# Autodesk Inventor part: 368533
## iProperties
Created: 2006-08
Part Number: 368533
Material: St
Description: Paßscheibe
Vendor: Autodesk Inc.
Document SubType Name: Modeling
Standard: DIN 988
Designer: I.Baliuc
Standards Organization: DIN
Language: de-DE
Size Designation: 25 x 35 x 0.5
Categories: <MemberInstance Version="R10.0.0"><Categories><Category DisplayName="Wellenteile" InternalName="7f7aeb1f-a693-4053-b835-cee3144e0d98" Mnemonic="SHFT"><Category
Density: 7.86 g/cm^3
Mass: 1.85197 g
Surface Area: 10.3673 cm^2
Volume: 0.235619 cm^3
Abmessung: 25x35x0.5
Author: T.Messerschmitt
Comments: DIN 988 - 25x35x0.5
Revision Number: 368533
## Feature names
1. Körper [Extrusion]
